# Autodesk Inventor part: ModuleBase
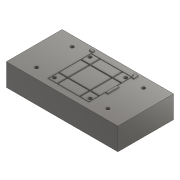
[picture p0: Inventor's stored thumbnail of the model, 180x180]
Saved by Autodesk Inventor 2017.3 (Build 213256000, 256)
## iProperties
Part Number: ModuleBase
Material: ステンレス鋼
Document SubType Name: Modeling
Designer: kyushu-hep
Density: 8 g/cm^3
Appearance: 半つや出し
Mass: 96.9479 g
Surface Area: 172.882 cm^2
Volume: 104.245 cm^3
Author: kyushu-hep
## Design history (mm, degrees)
sketch "スケッチ1"
  geometry: L1 (-50, 25)-(50, 25); L2 (50, 25)-(50, -25); L3 (50, -25)-(-50, -25); L4 (-50, -25)-(-50, 25); 1 further point
  constraints: 8 end point, 2 parallel, 1 horizontal, 1 perpendicular
  dimensions: "d0" = 100 distance of L2.end L3.end; "d1" = 50 distance of L1.end L2.end; "d22" = 25 distance from line of point (0, 0) L3; "d23" = 50 distance from line of L2 point (0, 0)
extrude "押し出し1" new body sketch "スケッチ1" distance "d2" = 20; taper "d3" = 0 deg
sketch "スケッチ4"
  geometry: L1 (17.855, 22.225)-(17.855, 20.225); L2 (17.855, 20.225)-(19.055, 20.225); L3 (19.055, 20.225)-(19.055, 18.225); L4 (19.055, 18.225)-(21.055, 18.225); L5 (21.055, 18.225)-(21.055, 22.225); L6 (21.055, 22.225)-(17.855, 22.225); L7 (21.055, 5)-(21.055, -5); L8 (21.055, -5)-(19.055, -5); L9 (19.055, -5)-(19.055, 5); L10 (19.055, 5)-(21.055, 5); L11 (-50, -25)-(50, -25) reference; L12 (-50, 25)-(-50, -25) reference; L13 (-21.055, 22.225)-(-17.855, 22.225); L14 (-17.855, 22.225)-(-17.855, 20.225); L15 (-17.855, 20.225)-(-21.055, 20.225); L16 (-21.055, 20.225)-(-21.055, 22.225); 1 further point
  constraints: 28 end point, 8 perpendicular, 4 point on line, 2 parallel, 1 collinear, 1 horizontal, 1 vertical
  dimensions: "d12" = 2 distance of L1.start L1.end; "d13" = 1.2 distance of L1.end L2.end; "d14" = 2 distance of L2.end L3.end; "d15" = 2 distance of L3.end L4.end; "d16" = 10 distance of L7.start L7.end; "d24" = 19.055 distance from line of L9 point (0, 0); "d25" = 22.225 distance from line of point (0, 0) L6; "d28" = 17.855 distance from line of point (0, 0) L14
extrude "押し出し4" join sketch "スケッチ4" distance "d29" = 1; taper "d30" = 0 deg
sketch "スケッチ6"
  geometry: L1 (20, 20)-(-20, 20); L2 (-20, 20)-(-20, -20); L3 (-20, -20)-(20, -20); L4 (20, -20)-(20, 20); L5 (20, 20)-(-20, -20); L6 (-20, 20)-(20, -20); C1 r 1.5 at (-32, -16); C2 r 1.5 at (-32, 16); C3 r 1.5 at (-16, -16); C4 r 1.5 at (-16, 16); C5 r 1.5 at (0, -16); C6 r 1.5 at (0, 16); C7 r 1.5 at (16, -16); C8 r 1.5 at (16, 16); C9 r 1.5 at (32, -16); C10 r 1.5 at (32, 16); 1 further point
  constraints: 12 end point, 10 centre point, 2 horizontal, 2 midpoint, 2 parallel, 1 perpendicular, 1 vertical, 18 other
  dimensions: "d41" = 3 diameter of C1; "d42" = 32 horizontal distance of point (0, 0) C1.centre; "d43" = 16 vertical distance of point (0, 0) C1.centre; "d44" = 40 distance of L3.end L2.end; "d45" = 40 distance of L2.end L1.end; "d48" = 32 distance of C1.centre C2.centre; "d51" = 16 distance of C1.centre C3.centre
extrude "押し出し8" cut sketch "スケッチ6" distance "d56" = 20; taper "d57" = 0 deg
sketch "スケッチ7"
  geometry: C1 r 0.5 at (-10, 10); C2 r 0.5 at (10, 10); C3 r 0.5 at (-10, -10); C4 r 0.5 at (10, -10); 1 further point
  constraints: 4 centre point
  dimensions: "d58" = 1 diameter of C1; "d59" = 10 horizontal distance of point (0, 0) C1.centre; "d60" = 10 horizontal distance of point (0, 0) C1.centre; "d61" = 1 diameter of C2; "d62" = 10 horizontal distance of point (0, 0) C2.centre; "d63" = 1 diameter of C3; "d64" = 10 horizontal distance of point (0, 0) C3.centre; "d65" = 1 diameter of C4
extrude "押し出し9" cut sketch "スケッチ7" distance "d66" = 10; taper "d67" = 0 deg
sketch "スケッチ9"
  geometry: L1 (18.5, -19.5)-(-18.5, -19.5); L2 (-18.5, -19.5)-(-18.5, 19.5); L3 (-18.5, 19.5)-(18.5, 19.5); L4 (18.5, 19.5)-(18.5, -19.5); L5 (18.5, -19.5)-(-18.5, 19.5); L6 (-18.5, -19.5)-(18.5, 19.5); L7 (-10.5, 10.5)-(-18, 10.5); L8 (-18, 10.5)-(-18, 19); L9 (-18, 19)-(-10.5, 19); L10 (-10.5, 19)-(-10.5, 10.5); L11 (-10.5, 10.5)-(-18, 19); L12 (-18, 10.5)-(-10.5, 19); L13 (18, 10.5)-(10.5, 10.5); L14 (10.5, 10.5)-(10.5, 19); L15 (10.5, 19)-(18, 19); L16 (18, 19)-(18, 10.5); L17 (-9.5, 19)-(9.5, 19); L18 (9.5, 19)-(9.5, 10.5); L19 (9.5, 10.5)-(-9.5, 10.5); L20 (-9.5, 10.5)-(-9.5, 19); L21 (-18, 9.5)-(-10.5, 9.5); L22 (-10.5, 9.5)-(-10.5, -9.5); L23 (-10.5, -9.5)-(-18, -9.5); L24 (-18, -9.5)-(-18, 9.5); L25 (-18, -10.5)-(-10.5, -10.5); L26 (-10.5, -10.5)-(-10.5, -19); L27 (-10.5, -19)-(-18, -19); L28 (-18, -19)-(-18, -10.5); L29 (-9.5, 9.5)-(9.5, 9.5); L30 (9.5, 9.5)-(9.5, -9.5); L31 (9.5, -9.5)-(-9.5, -9.5); L32 (-9.5, -9.5)-(-9.5, 9.5); L33 (10.5, 9.5)-(18, 9.5); L34 (18, 9.5)-(18, -9.5); L35 (18, -9.5)-(10.5, -9.5); L36 (10.5, -9.5)-(10.5, 9.5); L37 (-9.5, -10.5)-(9.5, -10.5); L38 (9.5, -10.5)-(9.5, -19); L39 (9.5, -19)-(-9.5, -19); L40 (-9.5, -19)-(-9.5, -10.5); L41 (10.5, -10.5)-(18, -10.5); L42 (18, -10.5)-(18, -19); L43 (18, -19)-(10.5, -19); L44 (10.5, -19)-(10.5, -10.5); 2 further points
  constraints: 88 end point, 20 parallel, 19 collinear, 10 horizontal, 10 perpendicular, 4 midpoint, 4 point on line
  dimensions: "d78" = 37 distance of L2.end L3.end; "d79" = 39 distance of L1.end L2.end; "d80" = 7.5 distance of L8.end L9.end; "d81" = 0.5 distance between parallel lines of L3 L9; "d82" = 0.5 distance between parallel lines of L2 L8; "d83" = 8.5 distance of L7.end L8.end; "d88" = 19 distance of L18.end L19.end; "d89" = 8.5 distance of L17.end L18.end; "d90" = 1 distance between parallel lines of L10 L20; "d92" = 19 distance of L21.end L22.end; "d93" = 1 distance between parallel lines of L21 L7; "d94" = 8.5 distance of L25.end L26.end; "d95" = 1 distance between parallel lines of L25 L23; "d96" = 8.5 distance of L13.end L14.end; "d97" = 1 distance between parallel lines of L14 L18
extrude "押し出し11" cut sketch "スケッチ9" distance "d98" = 1; taper "d99" = 0 deg
node "ソリッド1"
